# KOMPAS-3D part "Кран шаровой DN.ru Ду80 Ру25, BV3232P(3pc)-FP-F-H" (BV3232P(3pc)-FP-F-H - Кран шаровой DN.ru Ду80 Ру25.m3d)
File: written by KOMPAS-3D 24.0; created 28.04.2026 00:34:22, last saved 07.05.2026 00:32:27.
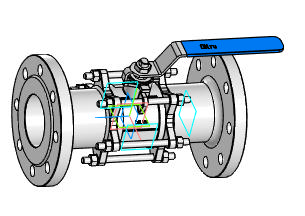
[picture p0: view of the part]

Document properties: Автор: Максим; Полное имя файла: BVxxP(3pc)-FP-F-H - Кран шаровой DN.ru Ду80 Ру25.cdw

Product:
- Body: Тело 1  | qty 1
    Масса: 14.35712
- Part/product: Кран шаровой DN.ru Ду80 Ру25  | designation BV3232P(3pc)-FP-F-H
    Масса: 16.665
    Раздел спецификации: Прочие изделия
    Форматы листов документа: A3
    Примечание: D160-22808

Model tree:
1. Операция без истории:1
2. Эскиз:1  (with: Ребро.Операция без истории:1)
3. Элемент выдавливания:1
     Расстояние 1 = 11
4. Скругление:1  (with: Ребро.Элемент выдавливания:1)
     Радиус = 4
5. Скругление:2  (with: Ребро.Элемент выдавливания:1)
     Радиус = 8
6. Эскиз:3  (with: Ребро.Элемент выдавливания:1)
7. Элемент выдавливания:2
     Расстояние 1 = 31
8. Фаска:1  (with: Ребро.Элемент выдавливания:2)
     Угол = 45; Длина 1 = 8; Длина 2 = 8
9. Скругление:3  (with: Ребро.Элемент выдавливания:1)
     Радиус = 4
10. Скругление:4  (with: Ребро.Элемент выдавливания:1)
     Радиус = 8
11. Эскиз:4  (with: Ребро.Элемент выдавливания:2)
12. Элемент выдавливания:3
     Расстояние 1 = 32
13. Скругление:5  (with: Ребро.Элемент выдавливания:3)
     Радиус = 10
14. Скругление:6  (with: Ребро.Элемент выдавливания:3)
     Радиус = 0.5
15. Эскиз:5  (with: Грань.Операция без истории:1, Ребро.Операция без истории:1)
16. Элемент выдавливания:4  (with: Грань.Операция без истории:1)
     Расстояние 2 = 310
17. Смещенная плоскость:1
     Расстояние = -95
18. Эскиз:6  (with: Ребро.Операция без истории:1)
19. Элемент выдавливания:5
     Расстояние 1 = 39
20. Зеркальный массив:1
21. Экземпляр ( 1 )
22. Экземпляр ( 2 )  (with: Элемент выдавливания:5)
23. Смещенная плоскость:2
     Расстояние = 49
24. Эскиз:7
25. Элемент выдавливания:6  (with: Грань.Операция без истории:1)
     Расстояние 1 = -4.78298
26. Эскиз:8
27. Элемент выдавливания:7
     Расстояние 1 = 44
28. Эскиз:10  (with: Грань.Операция без истории:1)
29. Элемент выдавливания:8
     Расстояние 1 = 10
30. Зеркальный массив:2  (with: Экземпляр ( 1 ), Экземпляр ( 2 ), Элемент выдавливания:8)
31. Эскиз:12  (with: Грань.Элемент выдавливания:8, Ребро.Операция без истории:1)
32. Элемент вращения:1
     Угол 1 = 360
33. Зеркальный массив:3  (with: Экземпляр ( 1 ), Экземпляр ( 2 ), Элемент вращения:1)
34. Смещенная плоскость:3
     Расстояние = 49
35. Эскиз:13
36. Элемент выдавливания:9  (with: Грань.Операция без истории:1)
     Расстояние 1 = -5.40968
37. Зеркальный массив:4  (with: Экземпляр ( 1 ), Экземпляр ( 2 ), Элемент выдавливания:7)
38. Эскиз:14  (with: Грань.Элемент выдавливания:3, Ребро.Скругление:6, Ребро.Элемент выдавливания:3)
39. Элемент выдавливания:10
     Расстояние 2 = 0.2

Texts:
  BV3232P(3pc)-FP-F-H
  DN80 PN25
